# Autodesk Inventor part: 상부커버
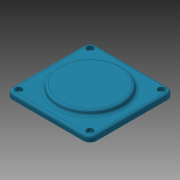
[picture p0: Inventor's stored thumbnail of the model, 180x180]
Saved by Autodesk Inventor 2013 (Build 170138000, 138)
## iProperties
Created: 2018-09
Part Number: 상부커버
Document SubType Name: Modeling
Density: 2.71 g/cm^3
Material: 알루미늄 6061
Mass: 284.928 g
Surface Area: 255.797 cm^2
Volume: 105.139 cm^3
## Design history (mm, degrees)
sketch "스케치5"
  geometry: L1 (-52.5, -52.5)-(52.5, -52.5); L2 (52.5, -52.5)-(52.5, 52.5); L3 (52.5, 52.5)-(-52.5, 52.5); L4 (-52.5, 52.5)-(-52.5, -52.5); L5 (-52.5, -52.5)-(52.5, 52.5); L6 (52.5, -52.5)-(-52.5, 52.5); 1 further point
  constraints: 12 end point, 2 midpoint, 2 parallel, 1 horizontal, 1 perpendicular
  dimensions: "d35" = 105 distance of L3.end L2.end; "d36" = 105 distance of L2.end L1.end
extrude "돌출4" new body sketch "스케치5" distance "d37" = 7; taper "d38" = 0 deg
fillet "모깎기4" dims "d39" = 8
sketch "스케치2"
  geometry: C1 r 40 at (0, 0); 2 further points
  constraints: 2 coincident, 1 centre point
  dimensions: "d4" = 80 diameter of C1
extrude "돌출3" join sketch "스케치2" distance "d5" = 6; taper "d6" = 0 deg
fillet "모깎기1" dims "d7" = 3
sketch "스케치4"
  geometry: L1 (52.5, -44.5)-(52.5, 44.5) reference; L2 (-44.5, -52.5)-(44.5, -52.5) reference; L3 (-52.5, 44.5)-(-52.5, -44.5) reference; L4 (44.5, 52.5)-(-44.5, 52.5) reference; A1 r 8 centre (44.5, 44.5) between (52.5, 44.5) and (44.5, 52.5) reference; A2 r 8 centre (44.5, -44.5) between (44.5, -52.5) and (52.5, -44.5) reference; A3 r 8 centre (-44.5, -44.5) between (-52.5, -44.5) and (-44.5, -52.5) reference; A4 r 8 centre (-44.5, 44.5) between (-44.5, 52.5) and (-52.5, 44.5) reference; 4 further points
  constraints: 4 coincident
hole "구멍3" sketch "스케치4" at (-44.5, 44.5), (-44.5, -44.5), (44.5, -44.5), (44.5, 44.5) diameter "d43" = 4.5; stored, may be unused: countersink angle "d47" = 90 deg, drill point angle "d49" = 118 deg; dims "d44" = 6, "d45" = 8, "d46" = 4.4, "d48" = 8
fillet "모깎기3" dims "d19" = 3
node "솔리드1"
node "솔리드2"
node "투영된 루프2"
